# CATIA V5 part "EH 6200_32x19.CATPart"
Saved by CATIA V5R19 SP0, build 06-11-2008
Definition: EH 6200_32x19
Nomenclature: EH 6200_32x19
Description: PART--DESC
Material "Steel": density 7860 kg/m3, Young's modulus 2e+11 Pa, Poisson ratio 0.266, thermal expansion 1.17e-05 1/K
Bounding box of the stored display mesh (mm): x -15.99 to 15.99, y -16 to 16, z 15 to 40.5
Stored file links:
  G:\UTB\Kombinované\Bakalářská práce\Catia\FORMA\EH 6200_32x19.CATPart
  D:\Aplikace\CATIA\Nová složka\win_b64\startup\materials\Catalog.CATMaterial
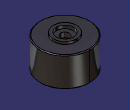
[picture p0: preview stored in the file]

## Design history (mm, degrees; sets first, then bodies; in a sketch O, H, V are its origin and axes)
Body1 "EH 6200_32x19" (main body)
  Solid1: solid without history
